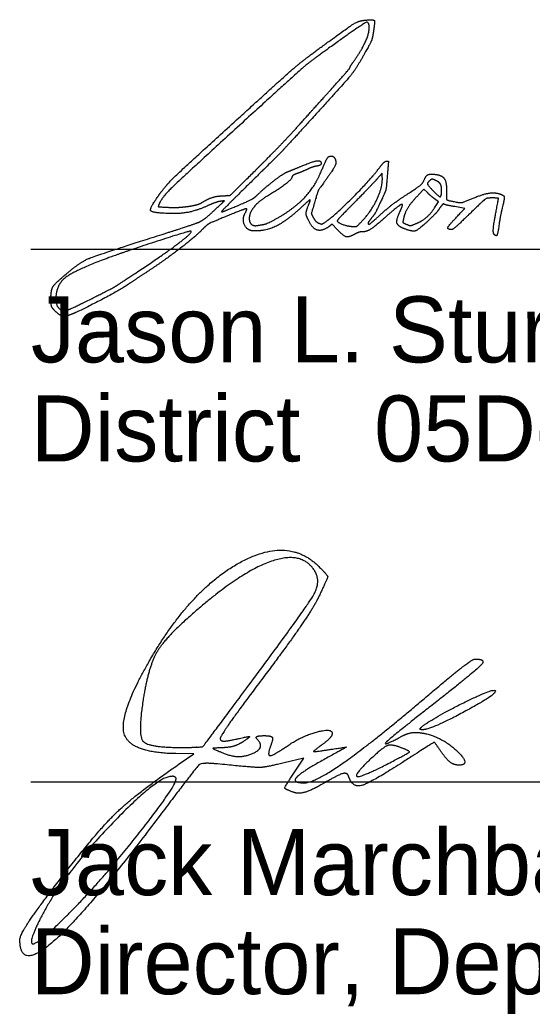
# Model space of a CAD drawing. Extents: x 0 to 34, y 0 to 22.
# Drawn here: x 24.804 to 25.89, y 8.24 to 10.348 of the extents above; entities that cross this region are included whole.
import ezdxf

# ---------------------------------------------------------------- set-up
doc = ezdxf.new("R2010")
doc.units = 0
doc.layers.add('SH_Data', color=7, linetype='Continuous')
doc.layers.add('SH_Text', color=7, linetype='Continuous')

msp = doc.modelspace()

# ---------------------------------------------------------------- linework, layer by layer
at = {"layer": 'SH_Data'}
for p, q in [((24.827, 9.8614), (28.327, 9.8614)), ((24.827, 8.7319), (28.327, 8.7319))]:
    msp.add_line(p, q, dxfattribs=at)
for points in [[(25.5726, 10.0132), (25.5721, 10.0226), (25.5611, 10.01)], [(25.6682, 9.9813), (25.661, 9.9884), (25.6496, 9.9767)], [(25.6832, 9.9491), (25.6918, 9.9618), (25.6836, 9.968)], [(25.7379, 9.9375), (25.7476, 9.9475), (25.7261, 9.9516)], [(25.4769, 9.9031), (25.4659, 9.9142), (25.4588, 9.9091)]]:
    msp.add_lwpolyline(points, dxfattribs=at)
for points in [[(25.4402, 10.288), (25.5014, 10.3329), (25.5234, 10.3462), (25.5382, 10.3472)], [(25.5447, 10.3291), (25.5454, 10.3458), (25.5284, 10.3375), (25.4586, 10.2873)], [(25.5155, 10.2649), (25.5285, 10.2832), (25.5442, 10.3177), (25.5447, 10.3291)], [(25.5382, 10.3472), (25.5544, 10.3483), (25.557, 10.3441), (25.5537, 10.3223)], [(25.5537, 10.3223), (25.5518, 10.3093), (25.5476, 10.2988), (25.5358, 10.2777)], [(25.2682, 10.1399), (25.3664, 10.2292), (25.4026, 10.2604), (25.4402, 10.288)], [(25.4586, 10.2873), (25.4178, 10.258), (25.3909, 10.2348), (25.2702, 10.1246)], [(25.5358, 10.2777), (25.5177, 10.2449), (25.4938, 10.2155), (25.4184, 10.1329)], [(25.4612, 10.1973), (25.4921, 10.2316), (25.5042, 10.2457), (25.5043, 10.2477)], [(25.5043, 10.2477), (25.5043, 10.2485), (25.5094, 10.2562), (25.5155, 10.2649)], [(25.3962, 10.125), (25.4181, 10.1494), (25.4474, 10.1819), (25.4612, 10.1973)], [(25.0949, 9.971), (25.1122, 9.9959), (25.1458, 10.0286), (25.2682, 10.1399)], [(25.2702, 10.1246), (25.1444, 10.01), (25.1042, 9.9704), (25.0983, 9.9557)], [(25.4184, 10.1329), (25.366, 10.0755), (25.3498, 10.0588), (25.2651, 9.9754)], [(25.3028, 10.0279), (25.3322, 10.0569), (25.3742, 10.1007), (25.3962, 10.125)], [(25.4406, 10.0212), (25.453, 10.0502), (25.4587, 10.0591), (25.4644, 10.0589)], [(25.4644, 10.0589), (25.4672, 10.0587), (25.4707, 10.0561), (25.4722, 10.053)], [(25.3708, 10.0252), (25.3745, 10.0267), (25.3882, 10.0323), (25.4012, 10.0376)], [(25.4012, 10.0376), (25.4255, 10.0477), (25.443, 10.0499), (25.4427, 10.0429)], [(25.4339, 10.0377), (25.4291, 10.0369), (25.4198, 10.0338), (25.4132, 10.0307)], [(25.4427, 10.0429), (25.4426, 10.0408), (25.4387, 10.0385), (25.4339, 10.0377)], [(25.4722, 10.053), (25.4756, 10.0459), (25.4697, 10.0322), (25.4532, 10.0093)], [(25.5633, 10.0302), (25.5703, 10.0396), (25.5782, 10.0477), (25.5809, 10.0481)], [(25.5809, 10.0481), (25.5855, 10.0488), (25.5856, 10.0469), (25.5832, 10.0177)], [(25.2385, 9.9749), (25.2491, 9.975), (25.2509, 9.9765), (25.3028, 10.0279)], [(25.3095, 9.9784), (25.3241, 9.9927), (25.3624, 10.0219), (25.3708, 10.0252)], [(25.3808, 10.014), (25.3807, 10.0096), (25.3503, 9.9866), (25.3266, 9.9728)], [(25.391, 10.0215), (25.3855, 10.0196), (25.3809, 10.0162), (25.3808, 10.014)], [(25.3857, 9.9511), (25.4046, 9.9657), (25.4317, 10.0003), (25.4406, 10.0212)], [(25.4132, 10.0307), (25.4065, 10.0276), (25.3966, 10.0234), (25.391, 10.0215)], [(25.4563, 9.9223), (25.4734, 9.9343), (25.5485, 10.0101), (25.5633, 10.0302)], [(25.5294, 9.9209), (25.5493, 9.9416), (25.5734, 9.9932), (25.5726, 10.0132)], [(25.5832, 10.0177), (25.5811, 9.9915), (25.5794, 9.984), (25.5727, 9.9699)], [(25.66, 10.0052), (25.6645, 10.0158), (25.6709, 10.0209), (25.6792, 10.0205)], [(25.6792, 10.0205), (25.6978, 10.0197), (25.7096, 10.0039), (25.7086, 9.9814)], [(25.4532, 10.0093), (25.4369, 9.9868), (25.4363, 9.9856), (25.4286, 9.9596)], [(25.5611, 10.01), (25.555, 10.0031), (25.5335, 9.9808), (25.5135, 9.9604)], [(25.625, 9.9777), (25.6454, 9.9909), (25.6581, 10.0008), (25.66, 10.0052)], [(25.6742, 10.0076), (25.6676, 10.0026), (25.6691, 9.9971), (25.6799, 9.9858)], [(25.6857, 10.0072), (25.6799, 10.0099), (25.6774, 10.01), (25.6742, 10.0076)], [(25.6981, 9.9827), (25.6986, 9.9942), (25.694, 10.0033), (25.6857, 10.0072)], [(25.1132, 9.9373), (25.0835, 9.9388), (25.0786, 9.9477), (25.0949, 9.971)], [(25.1914, 9.9612), (25.2035, 9.9687), (25.2241, 9.9747), (25.2385, 9.9749)], [(25.2651, 9.9754), (25.2461, 9.9567), (25.2309, 9.941), (25.2314, 9.9405)], [(25.2653, 9.9537), (25.2895, 9.9639), (25.3015, 9.9706), (25.3095, 9.9784)], [(25.3266, 9.9728), (25.3108, 9.9636), (25.2907, 9.9388), (25.2902, 9.9278)], [(25.5704, 9.9364), (25.5829, 9.9478), (25.6074, 9.9664), (25.625, 9.9777)], [(25.6496, 9.9767), (25.6346, 9.9615), (25.6207, 9.94), (25.6179, 9.9277)], [(25.6836, 9.968), (25.6791, 9.9714), (25.6721, 9.9773), (25.6682, 9.9813)], [(25.6799, 9.9858), (25.6923, 9.973), (25.6977, 9.972), (25.6981, 9.9827)], [(25.7086, 9.9814), (25.708, 9.9677), (25.7111, 9.9647), (25.7293, 9.9614)], [(25.7607, 9.9678), (25.7833, 9.9773), (25.8094, 9.9823), (25.8198, 9.9792)], [(25.8198, 9.9792), (25.8306, 9.976), (25.8321, 9.9699), (25.8271, 9.9493)], [(25.0983, 9.9557), (25.0967, 9.9516), (25.0987, 9.9511), (25.1185, 9.9502)], [(25.2005, 9.9529), (25.1782, 9.9427), (25.1406, 9.936), (25.1132, 9.9373)], [(25.1185, 9.9502), (25.1306, 9.9497), (25.1498, 9.9506), (25.1611, 9.9522)], [(25.1611, 9.9522), (25.1731, 9.954), (25.1857, 9.9577), (25.1914, 9.9612)], [(25.2285, 9.9628), (25.2235, 9.9621), (25.2108, 9.9576), (25.2005, 9.9529)], [(25.2158, 9.9435), (25.2375, 9.9638), (25.2377, 9.9641), (25.2285, 9.9628)], [(25.2314, 9.9405), (25.2318, 9.9401), (25.2471, 9.946), (25.2653, 9.9537)], [(25.4009, 9.9503), (25.3697, 9.9213), (25.3245, 9.8991), (25.2989, 9.9002)], [(25.3194, 9.9137), (25.3284, 9.9152), (25.3688, 9.938), (25.3857, 9.9511)], [(25.4193, 9.966), (25.4185, 9.9661), (25.4103, 9.959), (25.4009, 9.9503)], [(25.4151, 9.9242), (25.4106, 9.9339), (25.4109, 9.9418), (25.4163, 9.9553)], [(25.4163, 9.9553), (25.4187, 9.9612), (25.42, 9.966), (25.4193, 9.966)], [(25.4286, 9.9596), (25.422, 9.9371), (25.4219, 9.9366), (25.4264, 9.9281)], [(25.5135, 9.9604), (25.4934, 9.9401), (25.4769, 9.9226), (25.4769, 9.9216)], [(25.5727, 9.9699), (25.5591, 9.9409), (25.556, 9.9353), (25.5492, 9.927)], [(25.6153, 9.955), (25.6154, 9.9589), (25.5978, 9.9459), (25.5736, 9.9244)], [(25.6108, 9.9428), (25.6132, 9.9479), (25.6152, 9.9534), (25.6153, 9.955)], [(25.7031, 9.9572), (25.7023, 9.9581), (25.698, 9.9537), (25.6937, 9.9474)], [(25.7261, 9.9516), (25.7142, 9.9538), (25.7039, 9.9563), (25.7031, 9.9572)], [(25.7293, 9.9614), (25.7387, 9.9597), (25.7439, 9.9608), (25.7607, 9.9678)], [(25.8115, 9.97), (25.7959, 9.9706), (25.7876, 9.9654), (25.7555, 9.9341)], [(25.8098, 9.8929), (25.8071, 9.8959), (25.8097, 9.9194), (25.8174, 9.9598)], [(25.8174, 9.9598), (25.8192, 9.9693), (25.819, 9.9696), (25.8115, 9.97)], [(25.8271, 9.9493), (25.8247, 9.9394), (25.8216, 9.9236), (25.8203, 9.9142)], [(25.1818, 9.9181), (25.1889, 9.921), (25.2028, 9.9313), (25.2158, 9.9435)], [(25.243, 9.9317), (25.208, 9.9173), (25.2004, 9.9131), (25.1898, 9.9023)], [(25.285, 9.9472), (25.2843, 9.9479), (25.2654, 9.9409), (25.243, 9.9317)], [(25.2989, 9.9002), (25.2851, 9.9008), (25.2746, 9.9266), (25.2827, 9.9402)], [(25.2827, 9.9402), (25.2846, 9.9434), (25.2856, 9.9465), (25.285, 9.9472)], [(25.5425, 9.9174), (25.5423, 9.9125), (25.5505, 9.918), (25.5704, 9.9364)], [(25.6197, 9.9046), (25.6052, 9.9101), (25.6019, 9.9239), (25.6108, 9.9428)], [(25.6438, 9.9156), (25.6575, 9.9213), (25.6737, 9.9352), (25.6832, 9.9491)], [(25.6937, 9.9474), (25.6893, 9.9411), (25.6778, 9.9288), (25.6681, 9.9199)], [(25.7196, 9.9029), (25.7093, 9.9033), (25.7146, 9.9134), (25.7379, 9.9375)], [(25.7555, 9.9341), (25.7378, 9.9169), (25.7216, 9.9028), (25.7196, 9.9029)], [(25.1056, 9.8929), (25.1409, 9.9041), (25.1752, 9.9154), (25.1818, 9.9181)], [(25.2902, 9.9278), (25.2898, 9.9194), (25.2985, 9.9103), (25.306, 9.9115)], [(25.306, 9.9115), (25.3092, 9.912), (25.3153, 9.913), (25.3194, 9.9137)], [(25.4588, 9.9091), (25.4443, 9.8987), (25.4235, 9.9059), (25.4151, 9.9242)], [(25.4264, 9.9281), (25.4289, 9.9234), (25.434, 9.9182), (25.4378, 9.9167)], [(25.4378, 9.9167), (25.4435, 9.9144), (25.4464, 9.9153), (25.4563, 9.9223)], [(25.4769, 9.9216), (25.4767, 9.9185), (25.4983, 9.9103), (25.5084, 9.9097)], [(25.5084, 9.9097), (25.5167, 9.9091), (25.5196, 9.9107), (25.5294, 9.9209)], [(25.5736, 9.9244), (25.5549, 9.9077), (25.5378, 9.8978), (25.528, 9.8981)], [(25.5492, 9.927), (25.5456, 9.9225), (25.5426, 9.9182), (25.5425, 9.9174)], [(25.6179, 9.9277), (25.616, 9.9191), (25.6164, 9.9177), (25.6218, 9.9152)], [(25.6681, 9.9199), (25.6485, 9.902), (25.6366, 9.8982), (25.6197, 9.9046)], [(25.6218, 9.9152), (25.6305, 9.9113), (25.6338, 9.9114), (25.6438, 9.9156)], [(25.8203, 9.9142), (25.8175, 9.8944), (25.8143, 9.888), (25.8098, 9.8929)], [(24.8985, 9.8061), (24.9307, 9.8337), (24.9672, 9.849), (25.1056, 9.8929)], [(25.1671, 9.8997), (25.1657, 9.9011), (25.0352, 9.859), (24.9926, 9.8435)], [(25.0502, 9.8116), (25.1098, 9.851), (25.17, 9.8964), (25.1671, 9.8997)], [(25.1898, 9.9023), (25.1741, 9.8863), (25.1085, 9.8362), (25.0732, 9.8132)], [(25.5139, 9.8931), (25.501, 9.8862), (25.491, 9.8889), (25.4769, 9.9031)], [(25.528, 9.8981), (25.5256, 9.8982), (25.5192, 9.896), (25.5139, 9.8931)], [(24.9926, 9.8435), (24.9225, 9.8178), (24.8811, 9.7868), (24.8799, 9.7591)], [(24.8694, 9.7596), (24.8701, 9.7761), (24.8778, 9.7884), (24.8985, 9.8061)], [(24.9452, 9.7514), (24.9965, 9.777), (25.0065, 9.7828), (25.0502, 9.8116)], [(25.0732, 9.8132), (25.0583, 9.8035), (25.0389, 9.7907), (25.0302, 9.7847)], [(25.0302, 9.7847), (25.0154, 9.7745), (24.9292, 9.7296), (24.9117, 9.7229)], [(24.8827, 9.7263), (24.8732, 9.7345), (24.8688, 9.7456), (24.8694, 9.7596)], [(24.8799, 9.7591), (24.8793, 9.7459), (24.8894, 9.7314), (24.8995, 9.7307)], [(24.8995, 9.7307), (24.9016, 9.7306), (24.9221, 9.7399), (24.9452, 9.7514)], [(24.9117, 9.7229), (24.9004, 9.7186), (24.8904, 9.7198), (24.8827, 9.7263)]]:
    msp.add_open_spline(points, degree=2, dxfattribs=at)
at = {"layer": 'SH_Text'}
for p, q in [((25.2893, 8.937), (25.2893, 8.937)), ((25.6546, 8.8471), (25.6546, 8.8471)), ((25.6099, 8.8055), (25.6099, 8.8055))]:
    msp.add_line(p, q, dxfattribs=at)
for points in [[(25.1417, 8.77), (25.1724, 8.7912), (25.1345, 8.7919)], [(25.3846, 8.7502), (25.4058, 8.7825), (25.3641, 8.7724)]]:
    msp.add_lwpolyline(points, dxfattribs=at)
for points in [[(25.078, 8.9877), (25.1643, 9.1381), (25.3724, 9.2541), (25.438, 9.1885)], [(25.4291, 9.1793), (25.4031, 9.2213), (25.277, 9.1802), (25.1817, 9.0985)], [(25.2893, 8.937), (25.4107, 9.1004), (25.4431, 9.1566), (25.4291, 9.1793)], [(25.438, 9.1885), (25.4568, 9.1697), (25.4569, 9.1647), (25.4385, 9.1262)], [(25.4385, 9.1262), (25.4276, 9.1033), (25.3758, 9.0277), (25.3236, 8.9583)], [(25.1817, 9.0985), (25.115, 9.0415), (25.0762, 8.9774), (25.0651, 8.9061)], [(25.1345, 8.7919), (25.0366, 8.7936), (25.0132, 8.8747), (25.078, 8.9877)], [(25.6681, 8.9142), (25.7186, 8.9571), (25.7641, 8.9923), (25.7692, 8.9924)], [(25.7692, 8.9924), (25.7941, 8.9929), (25.7707, 8.9673), (25.6849, 8.9)], [(25.3236, 8.9583), (25.2714, 8.889), (25.2286, 8.8283), (25.2286, 8.8235)], [(25.1432, 8.8051), (25.1899, 8.8051), (25.1944, 8.8092), (25.2893, 8.937)], [(25.6546, 8.8471), (25.675, 8.865), (25.8071, 8.9308), (25.8122, 8.9256)], [(25.8122, 8.9256), (25.8184, 8.9194), (25.6758, 8.8426), (25.6581, 8.8426)], [(25.0651, 8.9061), (25.0537, 8.8328), (25.0751, 8.8051), (25.1432, 8.8051)], [(25.4068, 8.7301), (25.4298, 8.7301), (25.5559, 8.8189), (25.6681, 8.9142)], [(25.6849, 8.9), (25.5916, 8.827), (25.5702, 8.8055), (25.6141, 8.829)], [(25.3727, 8.8094), (25.4016, 8.8292), (25.4661, 8.8467), (25.4661, 8.8348)], [(25.4661, 8.8348), (25.4661, 8.8303), (25.4564, 8.8194), (25.4445, 8.8107)], [(25.6141, 8.829), (25.6267, 8.8357), (25.6506, 8.8378), (25.6672, 8.8336)], [(25.6581, 8.8426), (25.6533, 8.8426), (25.6518, 8.8446), (25.6546, 8.8471)], [(25.6672, 8.8336), (25.7033, 8.8245), (25.7617, 8.7676), (25.735, 8.7676)], [(25.2286, 8.8235), (25.2286, 8.8188), (25.2441, 8.8184), (25.263, 8.8228)], [(25.2786, 8.8181), (25.2683, 8.8112), (25.2486, 8.805), (25.2349, 8.8045)], [(25.239, 8.7918), (25.2689, 8.7798), (25.3251, 8.8044), (25.3077, 8.8218)], [(25.263, 8.8228), (25.2885, 8.8288), (25.2925, 8.8275), (25.2786, 8.8181)], [(25.3077, 8.8218), (25.3032, 8.8263), (25.3094, 8.8301), (25.3216, 8.8301)], [(25.3216, 8.8301), (25.3362, 8.8301), (25.3413, 8.8236), (25.3366, 8.8113)], [(25.3366, 8.8113), (25.3277, 8.788), (25.3405, 8.7874), (25.3727, 8.8094)], [(25.7002, 8.7922), (25.6834, 8.8163), (25.6814, 8.8159), (25.6156, 8.7735)], [(25.2349, 8.8045), (25.2124, 8.8036), (25.2129, 8.8023), (25.239, 8.7918)], [(25.4445, 8.8107), (25.4256, 8.7969), (25.4275, 8.7956), (25.4601, 8.8006)], [(25.4601, 8.8006), (25.4969, 8.8061), (25.4968, 8.8059), (25.4513, 8.7807)], [(25.6099, 8.8055), (25.5926, 8.8118), (25.5761, 8.8067), (25.5567, 8.7889)], [(25.5817, 8.7692), (25.6281, 8.7928), (25.6317, 8.7974), (25.6099, 8.8055)], [(25.735, 8.7676), (25.7254, 8.7676), (25.7097, 8.7787), (25.7002, 8.7922)], [(24.8907, 8.5278), (24.9684, 8.6283), (25.0485, 8.7056), (25.1417, 8.77)], [(25.2229, 8.7701), (25.1895, 8.7735), (25.1777, 8.763), (25.1011, 8.6613)], [(25.3641, 8.7724), (25.3237, 8.7627), (25.3014, 8.7623), (25.2229, 8.7701)], [(25.4513, 8.7807), (25.4002, 8.7525), (25.3805, 8.7301), (25.4068, 8.7301)], [(25.6156, 8.7735), (25.5467, 8.7291), (25.5092, 8.7194), (25.5011, 8.7437)], [(25.5567, 8.7889), (25.5125, 8.7484), (25.5237, 8.7396), (25.5817, 8.7692)], [(25.3834, 8.7101), (25.3652, 8.7171), (25.3653, 8.7208), (25.3846, 8.7502)], [(25.5011, 8.7437), (25.4983, 8.7523), (25.479, 8.7471), (25.45, 8.73)], [(25.1345, 8.7408), (25.1136, 8.7617), (24.8951, 8.536), (24.8488, 8.4457)], [(24.9189, 8.4644), (24.9865, 8.5335), (25.1422, 8.7331), (25.1345, 8.7408)], [(25.45, 8.73), (25.4244, 8.7148), (25.3944, 8.7059), (25.3834, 8.7101)], [(25.1011, 8.6613), (24.9487, 8.4592), (24.8036, 8.3306), (24.8036, 8.3976)], [(24.8036, 8.3976), (24.8036, 8.4072), (24.8428, 8.4658), (24.8907, 8.5278)], [(24.8488, 8.4457), (24.8175, 8.3847), (24.8492, 8.3932), (24.9189, 8.4644)]]:
    msp.add_open_spline(points, degree=2, dxfattribs=at)

# ---------------------------------------------------------------- texts
for s, p in [('Jason L. Sturgeon, P.E.', (24.827, 9.6214)), ('District       Deputy Director', (24.827, 9.4114)), ('              05', (24.827, 9.4114)), ('Jack Marchbanks, PhD', (24.827, 8.4919)), ('Director, Department of Transportation', (24.827, 8.2819))]:
    msp.add_text(s, height=0.14, dxfattribs=at).set_placement(p)

doc.saveas('drawing.dxf')
